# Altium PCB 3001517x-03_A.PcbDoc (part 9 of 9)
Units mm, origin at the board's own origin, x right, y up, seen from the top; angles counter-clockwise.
Board outline 100 x 72 mm, 10 copper layers (Top, GND_2, Signal_3, Signal_4, PWR_5, GND_6, Signal_7, Signal_8, GND_9, Bottom), stack 1.6 mm thick; 602 components, 497 nets, 2372 pads, 1602 vias.
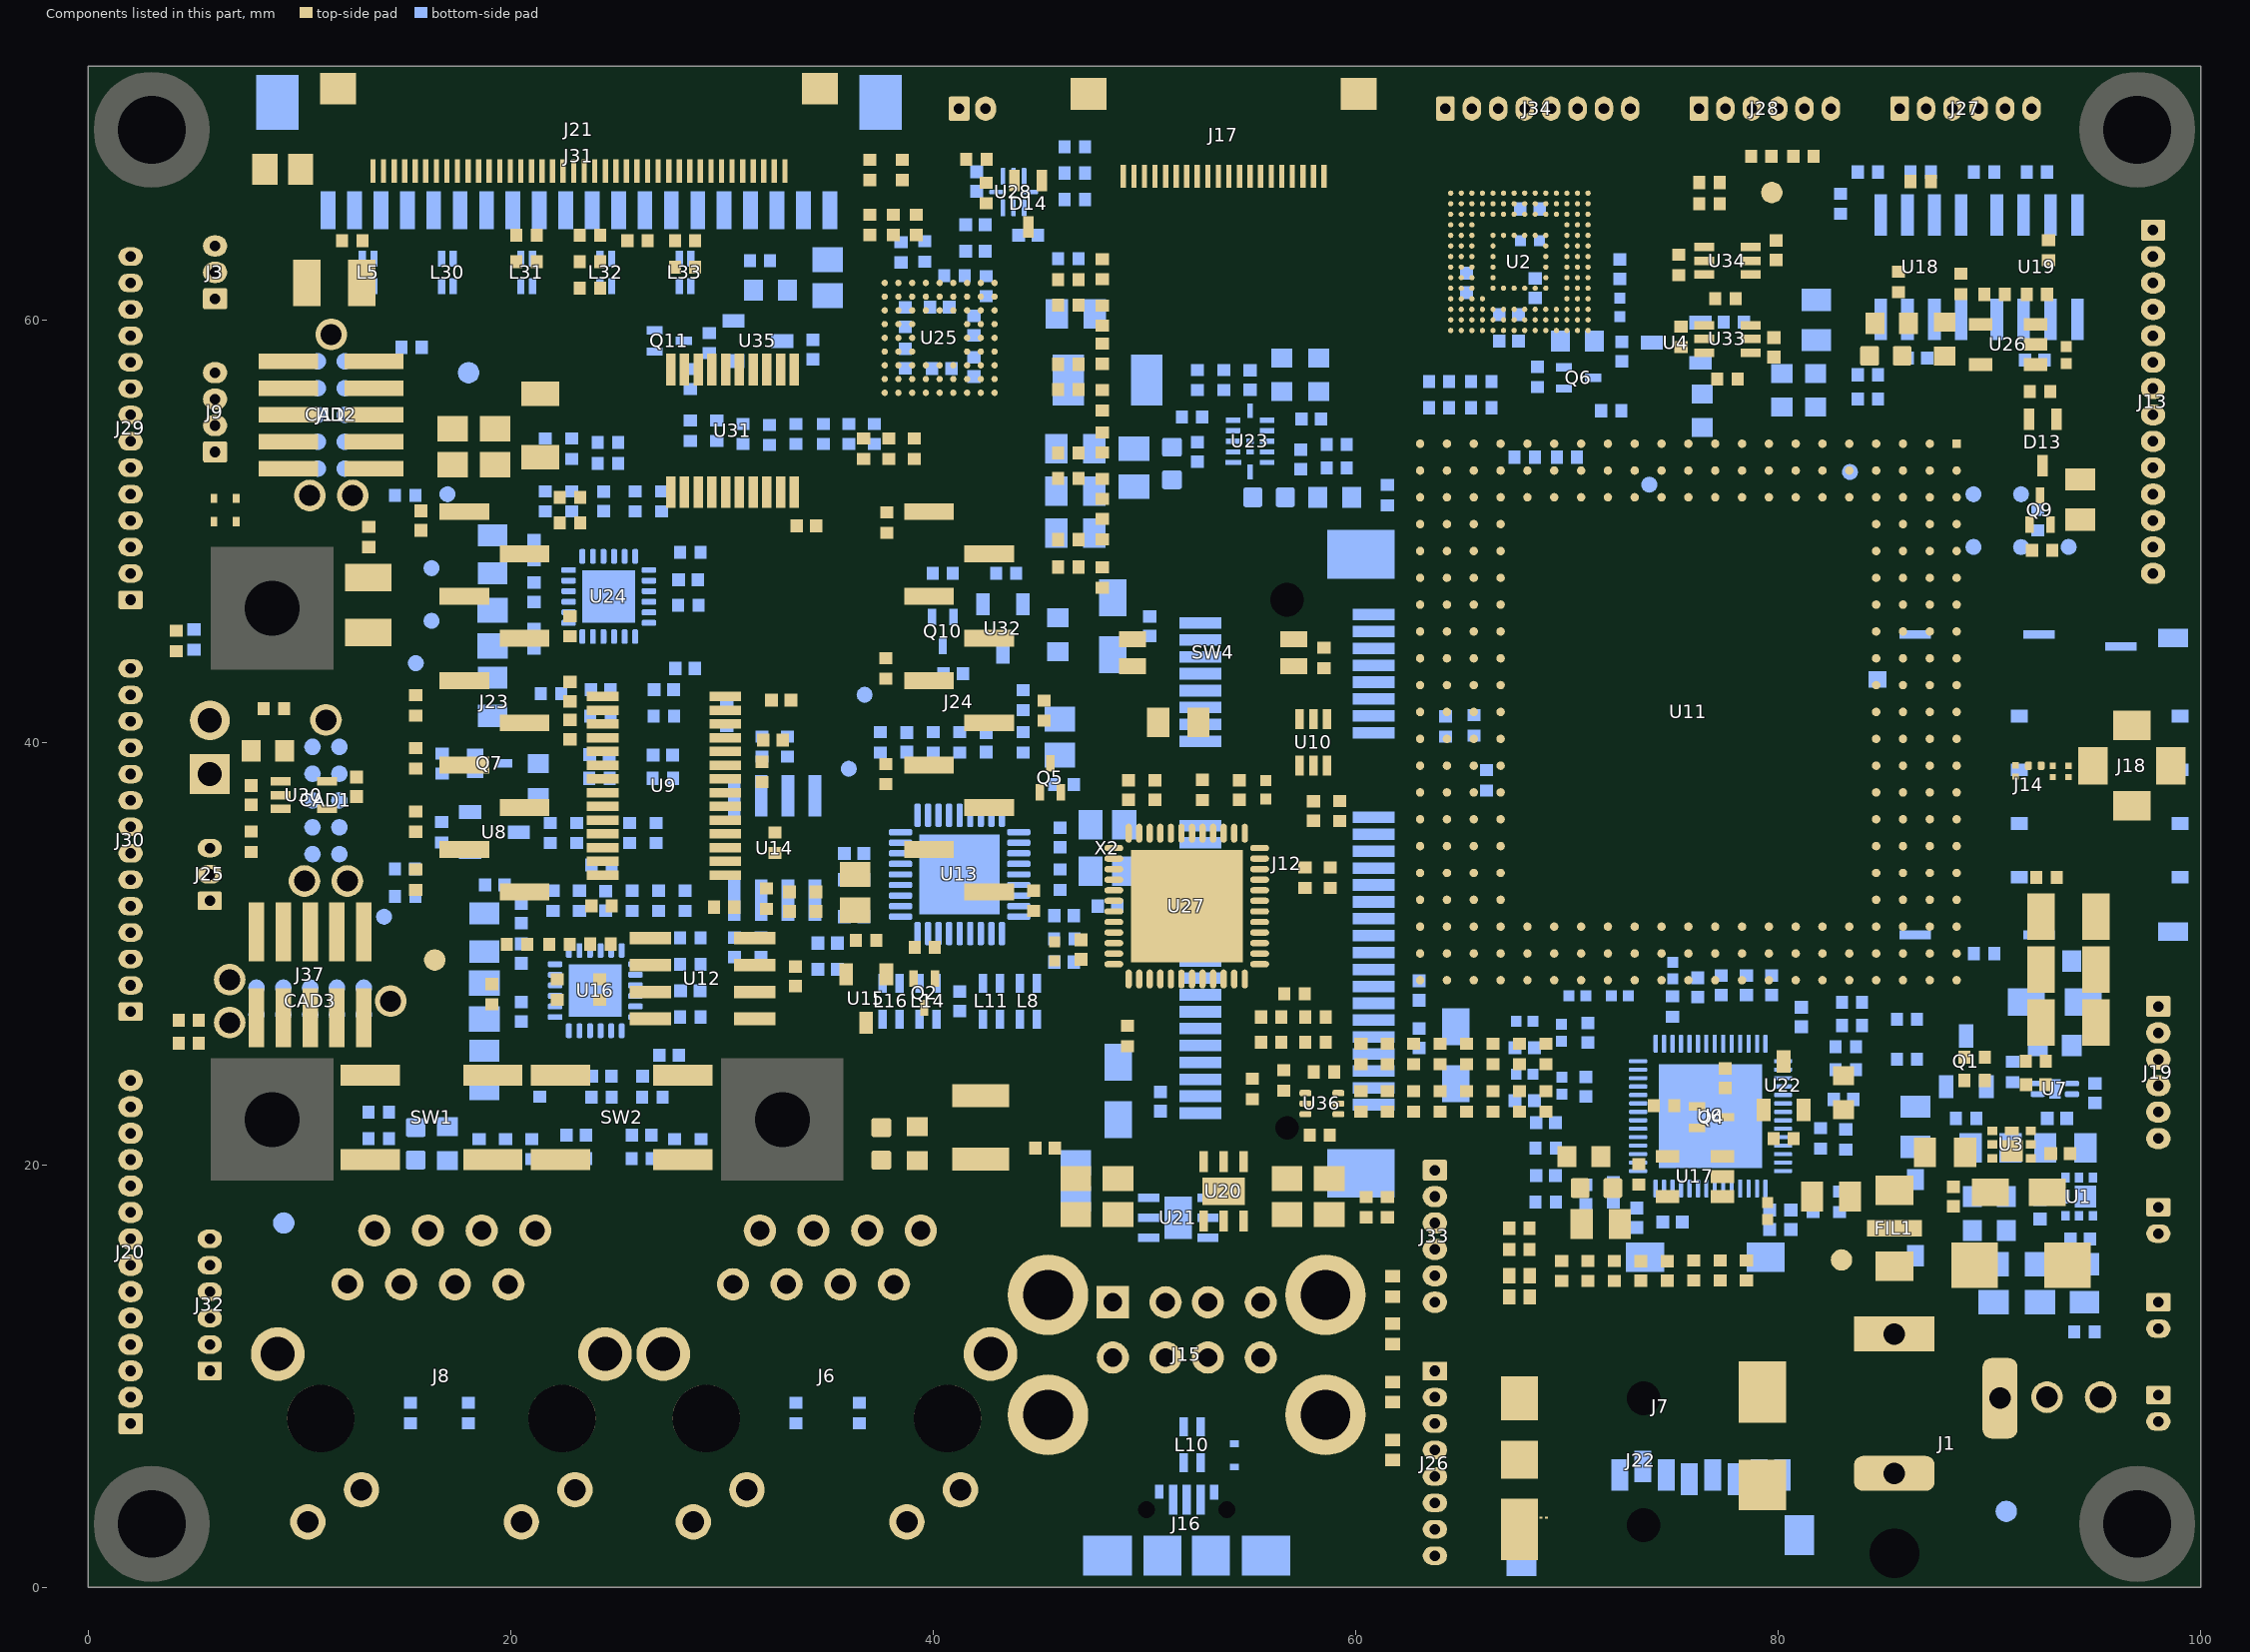
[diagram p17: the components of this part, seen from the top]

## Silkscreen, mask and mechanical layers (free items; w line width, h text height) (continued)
Sheet Graphics:
  drawing of 726 lines, arcs and shapes, not listed
  text "1" at 333.273,124.993 h4.57
  text "4" at -85.192,124.358 h4.57
  text "3" at 57.048,124.358 h4.57
  text "2" at 196.113,123.723 h4.57
  text "D" at -145.517,85.623 h7.11
  text "D" at 399.821,81.178 h7.11
  text "CUT OUT" at 45.695,72.644 h1.25
  text "CUT OUT" at 1.27,72.593 h1.25
  text "CUT OUT" at 153.492,72.593 h1.25
  text "CUT OUT" at 254.356,72.593 h1.25
  text "CUT OUT" at 101.981,63.754 h1.25 r90
  text "CUT OUT" at 204.394,63.703 h1.25 r90
  text "CUT OUT" at 306.908,63.043 h1.25 r90
  text "CUT OUT" at 71,39.5 h1.5
  text "CUT OUT" at 204.445,31.521 h1.25 r90
  text "CUT OUT" at -0.66,30.734 h1.25 r90
  text "CUT OUT" at 306.934,28.245 h1.25 r90
  text "CUT OUT" at 101.981,27.584 h1.25 r90
  text "CUT OUT" at 25.248,-2.616 h1.5
  text "CUT OUT" at 107.823,-2.718 h1.5
  text "CUT OUT" at 213.639,-2.896 h1.5
  text "CUT OUT" at 286.233,-2.896 h1.5
  text "C" at -145.517,-23.597 h7.11
  text "C" at 398.551,-23.597 h7.11
  text "1. Manufacture in accordance with IPC-6012, class 2. Inspect to IPC-A-600, class 2." at 185,-30 h6
  text "2. Manufacturing process and materials used must comply with ROHS directive / 2002/95/EC." at 185,-45 h6
  text "3. MATERIAL: ITEQ IT-180A /     Material should comply with IPC-4104/99/101/126 /     See Stack-up for details." at 185,-65 h6
  text "4. SURFACE FINISH: Apply ENIG to all exposed copper per IPC-4552." at 185,-72.5 h6
  text "5. Starting copper weight is 1/2oz. on all layers" at 185,-80 h6
  text "T" at -124.657,-87.923 h1.72
  text "a" at -123.97,-87.923 h1.72
  text "r" at -123.282,-87.923 h1.72
  text "g" at -122.791,-87.923 h1.72
  text "e" at -122.103,-87.923 h1.72
  text "t" at -121.317,-87.923 h1.72
  text "T" at -118.513,-87.923 h1.72
  text "o" at -117.825,-87.923 h1.72
  text "l" at -117.039,-87.923 h1.72
  text "+" at -116.352,-87.923 h1.72
  text "/" at -115.664,-87.923 h1.72
  text "-" at -115.074,-87.923 h1.72
  text "%" at -114.583,-87.923 h1.72
  text "L" at -112.82,-87.923 h1.72
  text "a" at -112.231,-87.923 h1.72
  text "y" at -111.543,-87.923 h1.72
  text "e" at -110.855,-87.923 h1.72
  text "r" at -110.069,-87.923 h1.72
  text "N" at -109.283,-87.923 h1.72
  text "o" at -108.301,-87.923 h1.72
  text "." at -107.515,-87.923 h1.72
  text "T" at -106.405,-87.923 h1.72
  text "r" at -105.717,-87.923 h1.72
  text "a" at -105.226,-87.923 h1.72
  text "c" at -104.538,-87.923 h1.72
  text "e" at -103.949,-87.923 h1.72
  text "C" at -102.868,-87.923 h1.72
  text "l" at -102.082,-87.923 h1.72
  text "e" at -101.689,-87.923 h1.72
  text "a" at -100.903,-87.923 h1.72
  text "r" at -100.215,-87.923 h1.72
  text "a" at -99.724,-87.923 h1.72
  text "n" at -99.036,-87.923 h1.72
  text "c" at -98.25,-87.923 h1.72
  text "e" at -97.661,-87.923 h1.72
  text "T" at -95.652,-87.923 h1.72
  text "r" at -94.964,-87.923 h1.72
  text "a" at -94.473,-87.923 h1.72
  text "c" at -93.785,-87.923 h1.72
  text "e" at -93.196,-87.923 h1.72
  text "W" at -92.115,-87.923 h1.72
  text "i" at -90.74,-87.923 h1.72
  text "d" at -90.347,-87.923 h1.72
  text "t" at -89.561,-87.923 h1.72
  text "h" at -89.069,-87.923 h1.72
  text "C" at -85.08,-87.923 h1.72
  text "h" at -84.294,-87.923 h1.72
  text "a" at -83.508,-87.923 h1.72
  text "r" at -82.82,-87.923 h1.72
  text "a" at -82.329,-87.923 h1.72
  text "c" at -81.641,-87.923 h1.72
  text "t" at -81.052,-87.923 h1.72
  text "e" at -80.561,-87.923 h1.72
  text "r" at -79.775,-87.923 h1.72
  text "i" at -79.283,-87.923 h1.72
  text "s" at -78.89,-87.923 h1.72
  text "t" at -78.301,-87.923 h1.72
  text "i" at -77.81,-87.923 h1.72
  text "c" at -77.417,-87.923 h1.72
  text "E" at -74.327,-87.923 h1.72
  text "d" at -73.639,-87.923 h1.72
  text "g" at -72.853,-87.923 h1.72
  text "e" at -72.166,-87.923 h1.72
  text "C" at -71.085,-87.923 h1.72
  text "o" at -70.299,-87.923 h1.72
  text "u" at -69.513,-87.923 h1.72
  text "p" at -68.727,-87.923 h1.72
  text "l" at -67.941,-87.923 h1.72
  text "e" at -67.548,-87.923 h1.72
  text "d" at -66.762,-87.923 h1.72
  text "I" at -126.013,-89.888 h1.72
  text "m" at -125.62,-89.888 h1.72
  text "p" at -124.441,-89.888 h1.72
  text "e" at -123.655,-89.888 h1.72
  text "d" at -122.869,-89.888 h1.72
  text "a" at -122.083,-89.888 h1.72
  text "n" at -121.395,-89.888 h1.72
  text "c" at -120.609,-89.888 h1.72
  text "e" at -120.02,-89.888 h1.72
  text "(" at -103.513,-89.888 h1.72
  text "M" at -103.022,-89.888 h1.72
  text "I" at -101.745,-89.888 h1.72
  text "L" at -101.352,-89.888 h1.72
  text ")" at -100.762,-89.888 h1.72
  text "(" at -93.754,-89.888 h1.72
  text "M" at -93.263,-89.888 h1.72
  text "I" at -91.986,-89.888 h1.72
  text "L" at -91.593,-89.888 h1.72
  text ")" at -91.004,-89.888 h1.72
  text "I" at -85.712,-89.888 h1.72
  text "m" at -85.319,-89.888 h1.72
  text "p" at -84.141,-89.888 h1.72
  text "e" at -83.355,-89.888 h1.72
  text "d" at -82.569,-89.888 h1.72
  text "a" at -81.783,-89.888 h1.72
  text "n" at -81.095,-89.888 h1.72
  text "c" at -80.309,-89.888 h1.72
  text "e" at -79.719,-89.888 h1.72
  text "(" at -78.639,-89.888 h1.72
  text "Z" at -78.147,-89.888 h1.72
  text "o" at -77.46,-89.888 h1.72
  text ")" at -76.674,-89.888 h1.72
  text "D" at -73.695,-89.888 h1.72
  text "i" at -72.81,-89.888 h1.72
  text "f" at -72.417,-89.888 h1.72
  text "f" at -71.926,-89.888 h1.72
  text "e" at -71.435,-89.888 h1.72
  text "r" at -70.649,-89.888 h1.72
  text "e" at -70.158,-89.888 h1.72
  text "n" at -69.372,-89.888 h1.72
  text "t" at -68.586,-89.888 h1.72
  text "i" at -68.095,-89.888 h1.72
  text "a" at -67.702,-89.888 h1.72
  text "l" at -67.014,-89.888 h1.72
  text "(" at -72.249,-91.853 h1.72
  text "Z" at -71.758,-91.853 h1.72
  text "d" at -71.07,-91.853 h1.72
  text "i" at -70.284,-91.853 h1.72
  text "f" at -69.891,-91.853 h1.72
  text "f" at -69.4,-91.853 h1.72
  text ")" at -68.909,-91.853 h1.72
  text "D" at -126.645,-93.916 h1.72
  text "I" at -125.761,-93.916 h1.72
  text "F" at -125.368,-93.916 h1.72
  text "F" at -124.68,-93.916 h1.72
  text "_" at -123.993,-93.916 h1.72
  text "1" at -123.305,-93.916 h1.72
  text "0" at -122.617,-93.916 h1.72
  text "0" at -121.929,-93.916 h1.72
  text "o" at -121.242,-93.916 h1.72
  text "h" at -120.456,-93.916 h1.72
  text "m" at -119.67,-93.916 h1.72
  text "1" at -116.796,-93.916 h1.72
  text "0" at -116.108,-93.916 h1.72
  text "3" at -110.471,-93.916 h1.72
  text "8" at -102.248,-93.916 h1.72
  text "5" at -92.58,-93.916 h1.72
  text "5" at -82.731,-93.916 h1.72
  text "5" at -82.043,-93.916 h1.72
  text "." at -81.355,-93.916 h1.72
  text "3" at -80.962,-93.916 h1.72
  text "6" at -80.274,-93.916 h1.72
  text "1" at -72.159,-93.916 h1.72
  text "0" at -71.471,-93.916 h1.72
  text "0" at -70.783,-93.916 h1.72
  text "." at -70.095,-93.916 h1.72
  text "3" at -69.702,-93.916 h1.72
  text "8" at -69.015,-93.916 h1.72
  text "6. SOLDER MASK: LPI over bare copper. / SOLDER MASK COLOR: BLUE" at 185,-95 h6
  text "D" at -126.645,-95.881 h1.72
  text "I" at -125.761,-95.881 h1.72
  text "F" at -125.368,-95.881 h1.72
  text "F" at -124.68,-95.881 h1.72
  text "_" at -123.993,-95.881 h1.72
  text "1" at -123.305,-95.881 h1.72
  text "0" at -122.617,-95.881 h1.72
  text "0" at -121.929,-95.881 h1.72
  text "o" at -121.242,-95.881 h1.72
  text "h" at -120.456,-95.881 h1.72
  text "m" at -119.67,-95.881 h1.72
  text "1" at -116.796,-95.881 h1.72
  text "0" at -116.108,-95.881 h1.72
  text "8" at -110.471,-95.881 h1.72
  text "8" at -102.248,-95.881 h1.72
  text "5" at -92.58,-95.881 h1.72
  text "5" at -82.731,-95.881 h1.72
  text "5" at -82.043,-95.881 h1.72
  text "." at -81.355,-95.881 h1.72
  text "3" at -80.962,-95.881 h1.72
  text "6" at -80.274,-95.881 h1.72
  text "1" at -72.159,-95.881 h1.72
  text "0" at -71.471,-95.881 h1.72
  text "0" at -70.783,-95.881 h1.72
  text "." at -70.095,-95.881 h1.72
  text "3" at -69.702,-95.881 h1.72
  text "8" at -69.015,-95.881 h1.72
  text "D" at -126.284,-97.846 h1.72
  text "I" at -125.4,-97.846 h1.72
  text "F" at -125.007,-97.846 h1.72
  text "F" at -124.319,-97.846 h1.72
  text "_" at -123.631,-97.846 h1.72
  text "9" at -122.943,-97.846 h1.72
  text "0" at -122.256,-97.846 h1.72
  text "o" at -121.568,-97.846 h1.72
  text "h" at -120.782,-97.846 h1.72
  text "m" at -119.996,-97.846 h1.72
  text "1" at -116.796,-97.846 h1.72
  text "0" at -116.108,-97.846 h1.72
  text "3" at -110.471,-97.846 h1.72
  text "8" at -102.248,-97.846 h1.72
  text "6" at -93.032,-97.846 h1.72
  text "." at -92.344,-97.846 h1.72
  text "5" at -91.951,-97.846 h1.72
  text "4" at -82.731,-97.846 h1.72
  text "8" at -82.043,-97.846 h1.72
  text "." at -81.355,-97.846 h1.72
  text "8" at -80.962,-97.846 h1.72
  text "8" at -80.274,-97.846 h1.72
  text "8" at -71.887,-97.846 h1.72
  text "9" at -71.2,-97.846 h1.72
  text "." at -70.512,-97.846 h1.72
  text "7" at -70.119,-97.846 h1.72
  text "6" at -69.431,-97.846 h1.72
  text "D" at -126.284,-99.811 h1.72
  text "I" at -125.4,-99.811 h1.72
  text "F" at -125.007,-99.811 h1.72
  text "F" at -124.319,-99.811 h1.72
  text "_" at -123.631,-99.811 h1.72
  text "9" at -122.943,-99.811 h1.72
  text "0" at -122.256,-99.811 h1.72
  text "o" at -121.568,-99.811 h1.72
  text "h" at -120.782,-99.811 h1.72
  text "m" at -119.996,-99.811 h1.72
  text "1" at -116.796,-99.811 h1.72
  text "0" at -116.108,-99.811 h1.72
  text "7" at -110.471,-99.811 h1.72
  text "8" at -102.248,-99.811 h1.72
  text "6" at -93.032,-99.811 h1.72
  text "." at -92.344,-99.811 h1.72
  text "5" at -91.951,-99.811 h1.72
  text "4" at -82.731,-99.811 h1.72
  text "8" at -82.043,-99.811 h1.72
  text "." at -81.355,-99.811 h1.72
  text "8" at -80.962,-99.811 h1.72
  text "8" at -80.274,-99.811 h1.72
  text "8" at -71.887,-99.811 h1.72
  text "9" at -71.2,-99.811 h1.72
  text "." at -70.512,-99.811 h1.72
  text "7" at -70.119,-99.811 h1.72
  text "6" at -69.431,-99.811 h1.72
  text "D" at -126.284,-101.776 h1.72
  text "I" at -125.4,-101.776 h1.72
  text "F" at -125.007,-101.776 h1.72
  text "F" at -124.319,-101.776 h1.72
  text "_" at -123.631,-101.776 h1.72
  text "9" at -122.943,-101.776 h1.72
  text "0" at -122.256,-101.776 h1.72
  text "o" at -121.568,-101.776 h1.72
  text "h" at -120.782,-101.776 h1.72
  text "m" at -119.996,-101.776 h1.72
  text "1" at -116.796,-101.776 h1.72
  text "0" at -116.108,-101.776 h1.72
  text "8" at -110.471,-101.776 h1.72
  text "8" at -102.248,-101.776 h1.72
  text "6" at -93.032,-101.776 h1.72
  text "." at -92.344,-101.776 h1.72
  text "5" at -91.951,-101.776 h1.72
  text "4" at -82.731,-101.776 h1.72
  text "8" at -82.043,-101.776 h1.72
  text "." at -81.355,-101.776 h1.72
  text "8" at -80.962,-101.776 h1.72
  text "8" at -80.274,-101.776 h1.72
  text "8" at -71.887,-101.776 h1.72
  text "9" at -71.2,-101.776 h1.72
  text "." at -70.512,-101.776 h1.72
  text "7" at -70.119,-101.776 h1.72
  text "6" at -69.431,-101.776 h1.72
  text "D" at -126.284,-103.741 h1.72
  text "I" at -125.4,-103.741 h1.72
  text "F" at -125.007,-103.741 h1.72
  text "F" at -124.319,-103.741 h1.72
  text "_" at -123.631,-103.741 h1.72
  text "9" at -122.943,-103.741 h1.72
  text "0" at -122.256,-103.741 h1.72
  text "o" at -121.568,-103.741 h1.72
  text "h" at -120.782,-103.741 h1.72
  text "m" at -119.996,-103.741 h1.72
  text "1" at -116.796,-103.741 h1.72
  text "0" at -116.108,-103.741 h1.72
  text "1" at -110.742,-103.741 h1.72
  text "0" at -110.054,-103.741 h1.72
  text "8" at -102.248,-103.741 h1.72
  text "5" at -92.58,-103.741 h1.72
  text "4" at -82.731,-103.741 h1.72
  text "8" at -82.043,-103.741 h1.72
  text "." at -81.355,-103.741 h1.72
  text "9" at -80.962,-103.741 h1.72
  text "5" at -80.274,-103.741 h1.72
  text "9" at -71.887,-103.741 h1.72
  text "0" at -71.2,-103.741 h1.72
  text "." at -70.512,-103.741 h1.72
  text "5" at -70.119,-103.741 h1.72
  text "2" at -69.431,-103.741 h1.72
  text "5" at -126.645,-105.706 h1.72
  text "0" at -125.958,-105.706 h1.72
  text "o" at -125.27,-105.706 h1.72
  text "h" at -124.484,-105.706 h1.72
  text "m" at -123.698,-105.706 h1.72
  text "_" at -122.519,-105.706 h1.72
  text "C" at -121.831,-105.706 h1.72
  text "H" at -121.045,-105.706 h1.72
  text "A" at -120.161,-105.706 h1.72
  text "R" at -119.277,-105.706 h1.72
  text "1" at -116.796,-105.706 h1.72
  text "0" at -116.108,-105.706 h1.72
  text "1" at -110.471,-105.706 h1.72
  text "N" at -103.061,-105.706 h1.72
  text "/" at -102.079,-105.706 h1.72
  text "A" at -101.49,-105.706 h1.72
  text "4" at -93.032,-105.706 h1.72
  text "." at -92.344,-105.706 h1.72
  text "7" at -91.951,-105.706 h1.72
  text "5" at -82.731,-105.706 h1.72
  text "0" at -82.043,-105.706 h1.72
  text "." at -81.355,-105.706 h1.72
  text "4" at -80.962,-105.706 h1.72
  text "3" at -80.274,-105.706 h1.72
  text "N" at -71.526,-105.706 h1.72
  text "/" at -70.544,-105.706 h1.72
  text "A" at -69.954,-105.706 h1.72
  text "5" at -126.645,-107.671 h1.72
  text "0" at -125.958,-107.671 h1.72
  text "o" at -125.27,-107.671 h1.72
  text "h" at -124.484,-107.671 h1.72
  text "m" at -123.698,-107.671 h1.72
  text "_" at -122.519,-107.671 h1.72
  text "C" at -121.831,-107.671 h1.72
  text "H" at -121.045,-107.671 h1.72
  text "A" at -120.161,-107.671 h1.72
  text "R" at -119.277,-107.671 h1.72
  text "1" at -116.796,-107.671 h1.72
  text "0" at -116.108,-107.671 h1.72
  text "3" at -110.471,-107.671 h1.72
  text "N" at -103.061,-107.671 h1.72
  text "/" at -102.079,-107.671 h1.72
  text "A" at -101.49,-107.671 h1.72
  text "5" at -92.58,-107.671 h1.72
  text "4" at -82.731,-107.671 h1.72
  text "8" at -82.043,-107.671 h1.72
  text "." at -81.355,-107.671 h1.72
  text "3" at -80.962,-107.671 h1.72
  text "8" at -80.274,-107.671 h1.72
  text "N" at -71.526,-107.671 h1.72
  text "/" at -70.544,-107.671 h1.72
  text "A" at -69.954,-107.671 h1.72
  text "5" at -126.645,-109.636 h1.72
  text "0" at -125.958,-109.636 h1.72
  text "o" at -125.27,-109.636 h1.72
  text "h" at -124.484,-109.636 h1.72
  text "m" at -123.698,-109.636 h1.72
  text "_" at -122.519,-109.636 h1.72
  text "C" at -121.831,-109.636 h1.72
  text "H" at -121.045,-109.636 h1.72
  text "A" at -120.161,-109.636 h1.72
  text "R" at -119.277,-109.636 h1.72
  text "1" at -116.796,-109.636 h1.72
  text "0" at -116.108,-109.636 h1.72
  text "7" at -110.471,-109.636 h1.72
  text "N" at -103.061,-109.636 h1.72
  text "/" at -102.079,-109.636 h1.72
  text "A" at -101.49,-109.636 h1.72
  text "5" at -92.58,-109.636 h1.72
  text "5" at -82.731,-109.636 h1.72
  text "0" at -82.043,-109.636 h1.72
  text "." at -81.355,-109.636 h1.72
  text "3" at -80.962,-109.636 h1.72
  text "5" at -80.274,-109.636 h1.72
  text "N" at -71.526,-109.636 h1.72
  text "/" at -70.544,-109.636 h1.72
  text "A" at -69.954,-109.636 h1.72
  text "5" at -126.645,-111.601 h1.72
  text "0" at -125.958,-111.601 h1.72
  text "o" at -125.27,-111.601 h1.72
  text "h" at -124.484,-111.601 h1.72
  text "m" at -123.698,-111.601 h1.72
  text "_" at -122.519,-111.601 h1.72
  text "C" at -121.831,-111.601 h1.72
  text "H" at -121.045,-111.601 h1.72
  text "A" at -120.161,-111.601 h1.72
  text "R" at -119.277,-111.601 h1.72
  text "1" at -116.796,-111.601 h1.72
  text "0" at -116.108,-111.601 h1.72
  text "8" at -110.471,-111.601 h1.72
  text "N" at -103.061,-111.601 h1.72
  text "/" at -102.079,-111.601 h1.72
  text "A" at -101.49,-111.601 h1.72
  text "5" at -92.58,-111.601 h1.72
  text "5" at -82.731,-111.601 h1.72
  text "0" at -82.043,-111.601 h1.72
  text "." at -81.355,-111.601 h1.72
  text "3" at -80.962,-111.601 h1.72
  text "5" at -80.274,-111.601 h1.72
  text "N" at -71.526,-111.601 h1.72
  text "/" at -70.544,-111.601 h1.72
  text "A" at -69.954,-111.601 h1.72
  text "5" at -126.645,-113.565 h1.72
  text "0" at -125.958,-113.565 h1.72
  text "o" at -125.27,-113.565 h1.72
  text "h" at -124.484,-113.565 h1.72
  text "m" at -123.698,-113.565 h1.72
  text "_" at -122.519,-113.565 h1.72
  text "C" at -121.831,-113.565 h1.72
  text "H" at -121.045,-113.565 h1.72
  text "A" at -120.161,-113.565 h1.72
  text "R" at -119.277,-113.565 h1.72
  text "1" at -116.796,-113.565 h1.72
  text "0" at -116.108,-113.565 h1.72
  text "1" at -110.742,-113.565 h1.72
  text "0" at -110.054,-113.565 h1.72
  text "N" at -103.061,-113.565 h1.72
  text "/" at -102.079,-113.565 h1.72
  text "A" at -101.49,-113.565 h1.72
  text "4" at -93.032,-113.565 h1.72
  text "." at -92.344,-113.565 h1.72
  text "7" at -91.951,-113.565 h1.72
  text "5" at -82.731,-113.565 h1.72
  text "0" at -82.043,-113.565 h1.72
  text "." at -81.355,-113.565 h1.72
  text "4" at -80.962,-113.565 h1.72
  text "3" at -80.274,-113.565 h1.72
  text "N" at -71.526,-113.565 h1.72
  text "/" at -70.544,-113.565 h1.72
  text "A" at -69.954,-113.565 h1.72
  text "7. SILKSCREEN: Apply on top and bottom sides of PCB. / High accuracy required for QR code on Bottom Overlay. / SILKSCREEN COLOR: WHITE" at 185,-117.5 h6
  text "Layer" at -125.494,-122 h2
  text "Name" at -111.989,-122 h2
  text "Material" at -81.156,-122 h2
  text "Thickness" at -18,-122 h2
  text "Constant" at 3.503,-122 h2
  text "Board Layer Stack" at 22.339,-122 h2
  text "1" at -125.494,-126 h2
  text "Top Overlay" at -111.989,-126 h2
  text "B" at -145.517,-129.642 h7.11
  text "B" at 398.551,-129.642 h7.11
  text "2" at -125.494,-130 h2
  text "Top Solder" at -111.989,-130 h2
  text "Dielectric" at -81.156,-130 h2
  text "0.50mil" at -18,-130 h2
  text "3.3" at 3.503,-130 h2
  text "8. GERBER FILE FORMAT: 274-X WITH 4/3 accuracy (XXXX.XXX). / Gerber and drill in mm." at 185,-132.5 h6
  text "3" at -125.494,-134 h2
  text "Top" at -111.989,-134 h2
  text "Copper" at -81.156,-134 h2
  text "1.70mil" at -18,-134 h2
  text "4" at -125.494,-138 h2
  text "Dielectric1" at -111.989,-138 h2
  text "IT-180A; 1086; Rc62%; (2GHz)" at -81.156,-138 h2
  text "2.99mil" at -18,-138 h2
  text "3.9" at 3.503,-138 h2
  text "5" at -125.494,-142 h2
  text "GND_2" at -111.989,-142 h2
  text "Copper" at -81.156,-142 h2
  text "0.70mil" at -18,-142 h2
  text "9. Maximum warp and twist per IPC-6012 of 0.75% inch/inch." at 185,-142.5 h6
  text "6" at -125.494,-146 h2
  text "Dielectric2" at -111.989,-146 h2
  text "IT-180A; 2-1080; (2GHz)" at -81.156,-146 h2
  text "5.00mil" at -18,-146 h2
  text "3.7" at 3.503,-146 h2
  text "7" at -125.494,-150 h2
  text "Signal_3" at -111.989,-150 h2
  text "Copper" at -81.156,-150 h2
  text "0.70mil" at -18,-150 h2
  text "8" at -125.494,-154 h2
  text "Dielectric3" at -111.989,-154 h2
  text "IT-180A; 1067; Rc71%; (2GHz) x2" at -81.156,-154 h2
  text "5.00mil" at -18,-154 h2
  text "3.9" at 3.503,-154 h2
  text "9" at -125.494,-158 h2
  text "Signal_4" at -111.989,-158 h2
  text "Copper" at -81.156,-158 h2
  text "0.70mil" at -18,-158 h2
  text "10. Copper thieving is NOT allowed within board outline. / Thieving may be placed in array rails." at 185,-160 h6
  text "10" at -125.494,-162 h2
  text "Dielectric 13" at -111.989,-162 h2
  text "IT-180A; 2-1080; (2GHz)" at -81.156,-162 h2
  text "5.00mil" at -18,-162 h2
  text "3.7" at 3.503,-162 h2
  text "11" at -125.494,-166 h2
  text "PWR_5" at -111.989,-166 h2
  text "Copper" at -81.156,-166 h2
  text "0.70mil" at -18,-166 h2
  text "12" at -125.494,-170 h2
  text "Dielectric6" at -111.989,-170 h2
  text "IT-180A" at -81.156,-170 h2
  text "17.99mil" at -18,-170 h2
  text "3.9" at 3.503,-170 h2
  text "13" at -125.494,-174 h2
  text "GND_6" at -111.989,-174 h2
  text "Copper" at -81.156,-174 h2
  text "0.70mil" at -18,-174 h2
  text "14" at -125.494,-178 h2
  text "Dielectric9" at -111.989,-178 h2
  text "IT-180A; 2-1080; (2GHz)" at -81.156,-178 h2
  text "5.00mil" at -18,-178 h2
  text "3.7" at 3.503,-178 h2
  text "15" at -125.494,-182 h2
  text "Signal_7" at -111.989,-182 h2
  text "Copper" at -81.156,-182 h2
  text "0.70mil" at -18,-182 h2
  text "11. Plated holes are specified as finished hole sizes (see table). / Plated hole tolerance ±0.003\" (±76µm) / NPTH tolerance ±0.0015\" (±38.1µm)" at 185,-182.5 h6
  text "16" at -125.494,-186 h2
  text "Dielectric10" at -111.989,-186 h2
  text "IT-180A; 1067; Rc71%; (2GHz) x2" at -81.156,-186 h2
  text "5.00mil" at -18,-186 h2
  text "3.9" at 3.503,-186 h2
  text "17" at -125.494,-190 h2
  text "Signal_8" at -111.989,-190 h2
  text "Copper" at -81.156,-190 h2
  text "0.70mil" at -18,-190 h2
  text "12. Slot/Cut-Out tolerance ±0.005\" (±127µm)" at 185,-190 h6
  text "18" at -125.494,-194 h2
  text "Dielectric 12" at -111.989,-194 h2
  text "IT-180A; 2-1080; (2GHz)" at -81.156,-194 h2
  text "5.00mil" at -18,-194 h2
  text "3.7" at 3.503,-194 h2
  text "19" at -125.494,-198 h2
  text "GND_9" at -111.989,-198 h2
  text "Copper" at -81.156,-198 h2
  text "0.70mil" at -18,-198 h2
  text "13. See table for controlled impedance trace widths." at 185,-200 h6
  text "20" at -125.494,-202 h2
  text "Dielectric11" at -111.989,-202 h2
  text "IT-180A; 1086; Rc62%; (2GHz)" at -81.156,-202 h2
  text "2.99mil" at -18,-202 h2
  text "3.9" at 3.503,-202 h2
  text "21" at -125.494,-206 h2
  text "Bottom" at -111.989,-206 h2
  text "Copper" at -81.156,-206 h2
  text "1.70mil" at -18,-206 h2
  text "14. Finished thickness is 0.062\" ±0.006\" (1.57 ± 157µm)" at 185,-207.5 h6
  text "22" at -125.494,-210 h2
  text "Bottom Solder" at -111.989,-210 h2
  text "Dielectric" at -81.156,-210 h2
  text "0.50mil" at -18,-210 h2
  text "3.3" at 3.503,-210 h2
  text "23" at -125.494,-214 h2
  text "Bottom Overlay" at -111.989,-214 h2
  text "15. Intentional short: NetNT1-1 to GND" at 185,-215 h6
  text "A" at -145.085,-222.352 h7.11
  text "A" at 398.983,-222.352 h7.11
  text "CAD GENERATED:" at 337.718,-227.432 h1.27
  text "CAD GENERATED:" at 337.718,-227.432 h1.27
  text ".pcb_File_Name_No_Path" at 353.212,-227.432 h2.17
  text "EXCEPT AS MAY BE OTHERWISE PROVIDED BY" at 238.658,-231.496 h2.17
  text "WIRELESS DESIGN SERVICES" at 332.638,-233.02 h2.54
  text "CONTRACT, THIS DOCUMENT IS THE PROPERTY" at 238.658,-233.528 h2.17
  text "OF DIGI INTERNATIONAL.  IF RELEASED TO OTHER" at 238.658,-235.56 h2.17
  text "11001 Bren Road East" at 332.638,-236.576 h2.54
  text "SOURCES, IT SHALL BE RECEIVED BY SUCH" at 238.658,-237.592 h2.17
  text "SOURCES IN TOTAL CONFIDENCE AND SHALL NOT" at 238.658,-239.624 h2.17
  text "Minnetonka, MN 55343" at 333.146,-240.132 h2.54
  text "BE RELEASED TO ANY THIRD PARTY OR PARTIES," at 238.658,-241.656 h2.17
  text "NOR USED FOR MANUFACTURE OR SALE OF THE" at 238.658,-243.688 h2.17
  text "ARTICLES WITHOUT PRIOR WRITTEN" at 238.658,-245.72 h2.17
  text "DIGI INTERNATIONAL" at 328.574,-246.228 h2.54
  text "AUTHORIZATION." at 238.658,-247.752 h2.17
  text "ConnectCore for i.MX6UL" at 323.596,-250.444 h2.54
  text "ENGINEER" at 238.15,-254.356 h1.27
  text "SINGLE BOARD COMPUTER (SBC)" at 315.976,-254.508 h2.54
  text "SEBASTIEN MEYER" at 255.524,-255.016 h1.27
  text "PCB DESIGNER" at 238.15,-259.436 h1.27
  text "SIZE" at 291.49,-259.436 h1.27
  text "CAGE NO." at 299.618,-259.436 h1.27
  text "PCB NO." at 327.558,-259.436 h1.27
  text "REV." at 389.534,-259.436 h1.27
  text "JOSH FLAGSTAD" at 255.524,-260.096 h1.27
  text "30015172-03" at 343.5,-263.5 h2.54
  text "DATE" at 238.15,-264.008 h1.27
  text "C" at 291.998,-264.008 h2.54
  text "A" at 389.534,-264.008 h2.54
  text ".Print_Date" at 254.914,-265.024 h1.27
  text "JIRA EPIC:" at 238.15,-269.088 h1.27
  text "CC6UL-244" at 254.914,-270.612 h1.27
  text ".Print_Scale" at 289.458,-270.612 h1.27
  text "SVN HEAD REV:" at 314.858,-270.612 h1.27
  text ".VersionControl_RevNumber" at 330.606,-270.612 h1.27
  text "SHEET:" at 352.958,-270.612 h1.27
  text "1 OF 1" at 371.5,-270.612 h1.27
  text "1" at 333.273,-280.137 h4.57
  text "4" at -85.192,-280.772 h4.57
  text "3" at 57.048,-280.772 h4.57
  text "2" at 196.113,-281.407 h4.57
Drill Drawing:
  circle w0.1: c21.781,-72.167 r0.5
  circle w0.1: c21.781,-72.167 r0.833
  lines w0.1: 19.5,-104.125 166.639,-104.125 ; 19.5,-29.125 166.639,-29.125 ; 32.792,-107.875 32.792,-25.375 ; 48.738,-107.875 48.738,-25.375 ; 77.179,-107.875 77.179,-25.375 ; 105.621,-107.875 105.621,-25.375 ; 135.482,-107.875 135.482,-25.375 ; 147.649,-107.875 147.649,-25.375 ; 19.5,-107.875 166.639,-107.875 166.639,-25.375 19.5,-25.375 19.5,-107.875 ; 20.948,-95.083 21.365,-95.083 21.365,-95.5 22.198,-95.5 22.198,-95.083 22.615,-95.083 22.615,-94.25 22.198,-94.25 22.198,-93.833 21.365,-93.833 21.365,-94.25 20.948,-94.25 20.948,-95.083 ; 20.948,-87.583 21.365,-87.583 21.781,-88 22.198,-87.583 22.615,-87.583 22.198,-87.167 22.615,-86.75 22.198,-86.75 21.781,-86.333 21.365,-86.75 20.948,-86.75 21.365,-87.167 20.948,-87.583 ; 20.948,-61.333 21.365,-61.333 21.781,-61.75 22.198,-61.333 22.615,-61.333 22.198,-60.917 22.615,-60.5 22.198,-60.5 21.781,-60.083 21.365,-60.5 20.948,-60.5 21.365,-60.917 20.948,-61.333 ; 20.948,-54.25 22.615,-54.25 22.615,-52.583 20.948,-52.583 20.948,-54.25 ; 20.948,-35.5 21.781,-35.083 22.615,-35.5 22.198,-34.667 22.615,-33.833 21.781,-34.25 20.948,-33.833 21.365,-34.667 20.948,-35.5 ; 21.281,-61.167 21.531,-61.167 21.781,-61.417 22.031,-61.167 22.281,-61.167 22.031,-60.917 22.281,-60.667 22.031,-60.667 21.781,-60.417 21.531,-60.667 21.281,-60.667 21.531,-60.917 21.281,-61.167 ; 21.281,-35.167 21.781,-34.917 22.281,-35.167 22.031,-34.667 22.281,-34.167 21.781,-34.417 21.281,-34.167 21.531,-34.667 21.281,-35.167
  text ".Layer_Name" at 35.736,-19.262 h2.54
  text "Symbol" at 21.75,-28 h1.8
  text "Count" at 33.917,-28 h1.8
  text "Hole Size" at 49.863,-28 h1.8
  text "Hole Length" at 78.304,-28 h1.8
  text "Rout Path Length" at 106.746,-28 h1.8
  text "Plated" at 136.607,-28 h1.8
  text "Hole Type" at 148.774,-28 h1.8
  text "600" at 33.917,-31.75 h1.5
  text "0.200mm (7.87mil)" at 49.863,-31.75 h1.5
  text "-" at 78.304,-31.75 h1.5
  text "-" at 106.746,-31.75 h1.5
  text "PTH" at 136.607,-31.75 h1.5
  text "Round" at 148.774,-31.75 h1.5
  text "W" at 21.126,-31.85 h1.67
  text "1002" at 33.917,-35.5 h1.5
  text "0.250mm (9.84mil)" at 49.863,-35.5 h1.5
  text "-" at 78.304,-35.5 h1.5
  text "-" at 106.746,-35.5 h1.5
  text "PTH" at 136.607,-35.5 h1.5
  text "Round" at 148.774,-35.5 h1.5
  text "120" at 33.917,-39.25 h1.5
  text "0.500mm (19.69mil)" at 49.863,-39.25 h1.5
  text "-" at 78.304,-39.25 h1.5
  text "-" at 106.746,-39.25 h1.5
  text "PTH" at 136.607,-39.25 h1.5
  text "Round" at 148.774,-39.25 h1.5
  text "H" at 21.126,-39.35 h1.67
  text "2" at 33.917,-43 h1.5
  text "0.813mm (32.00mil)" at 49.863,-43 h1.5
  text "-" at 78.304,-43 h1.5
  text "-" at 106.746,-43 h1.5
  text "NPTH" at 136.607,-43 h1.5
  text "Round" at 148.774,-43 h1.5
  text "S" at 21.126,-43.1 h1.67
  text "10" at 33.917,-46.75 h1.5
  text "0.889mm (35.00mil)" at 49.863,-46.75 h1.5
  text "-" at 78.304,-46.75 h1.5
  text "-" at 106.746,-46.75 h1.5
  text "PTH" at 136.607,-46.75 h1.5
  text "Round" at 148.774,-46.75 h1.5
  text "K" at 21.126,-46.85 h1.67
  text "14" at 33.917,-50.5 h1.5
  text "0.900mm (35.43mil)" at 49.863,-50.5 h1.5
  text "-" at 78.304,-50.5 h1.5
  text "-" at 106.746,-50.5 h1.5
  text "PTH" at 136.607,-50.5 h1.5
  text "Round" at 148.774,-50.5 h1.5
  text "J" at 21.126,-50.6 h1.67
  text "9" at 33.917,-54.25 h1.5
  text "0.991mm (39.00mil)" at 49.863,-54.25 h1.5
  text "-" at 78.304,-54.25 h1.5
  text "-" at 106.746,-54.25 h1.5
  text "NPTH" at 136.607,-54.25 h1.5
  text "Round" at 148.774,-54.25 h1.5
  text "8" at 33.917,-58 h1.5
  text "1.016mm (40.00mil)" at 49.863,-58 h1.5
  text "-" at 78.304,-58 h1.5
  text "-" at 106.746,-58 h1.5
  text "PTH" at 136.607,-58 h1.5
  text "Round" at 148.774,-58 h1.5
  text "I" at 21.404,-58.1 h1.67
  text "2" at 33.917,-61.75 h1.5
  text "1.020mm (40.16mil)" at 49.863,-61.75 h1.5
  text "-" at 78.304,-61.75 h1.5
  text "-" at 106.746,-61.75 h1.5
  text "PTH" at 136.607,-61.75 h1.5
  text "Round" at 148.774,-61.75 h1.5
  text "1" at 33.917,-65.5 h1.5
  text "1.100mm (43.31mil)" at 49.863,-65.5 h1.5
  text "-" at 78.304,-65.5 h1.5
  text "-" at 106.746,-65.5 h1.5
  text "NPTH" at 136.607,-65.5 h1.5
  text "Round" at 148.774,-65.5 h1.5
  text "R" at 21.126,-65.6 h1.67
  text "2" at 33.917,-69.25 h1.5
  text "1.143mm (45.00mil)" at 49.863,-69.25 h1.5
  text "-" at 78.304,-69.25 h1.5
  text "-" at 106.746,-69.25 h1.5
  text "PTH" at 136.607,-69.25 h1.5
  text "Round" at 148.774,-69.25 h1.5
  text "V" at 21.126,-69.35 h1.67
  text "3" at 33.917,-73 h1.5
  text "1.600mm (62.99mil)" at 49.863,-73 h1.5
  text "-" at 78.304,-73 h1.5
  text "-" at 106.746,-73 h1.5
  text "NPTH" at 136.607,-73 h1.5
  text "Round" at 148.774,-73 h1.5
  text "4" at 33.917,-76.75 h1.5
  text "1.600mm (63.00mil)" at 49.863,-76.75 h1.5
  text "-" at 78.304,-76.75 h1.5
  text "-" at 106.746,-76.75 h1.5
  text "PTH" at 136.607,-76.75 h1.5
  text "Round" at 148.774,-76.75 h1.5
  text "M" at 21.126,-76.85 h1.67
  text "1" at 33.917,-80.5 h1.5
  text "2.362mm (93.00mil)" at 49.863,-80.5 h1.5
  text "-" at 78.304,-80.5 h1.5
  text "-" at 106.746,-80.5 h1.5
  text "NPTH" at 136.607,-80.5 h1.5
  text "Round" at 148.774,-80.5 h1.5
  text "O" at 21.126,-80.6 h1.67
  text "4" at 33.917,-84.25 h1.5
  text "2.362mm (93.00mil)" at 49.863,-84.25 h1.5
  text "-" at 78.304,-84.25 h1.5
  text "-" at 106.746,-84.25 h1.5
  text "PTH" at 136.607,-84.25 h1.5
  text "Round" at 148.774,-84.25 h1.5
  text "T" at 21.126,-84.35 h1.67
  text "3" at 33.917,-88 h1.5
  text "2.600mm (102.36mil)" at 49.863,-88 h1.5
  text "-" at 78.304,-88 h1.5
  text "-" at 106.746,-88 h1.5
  text "PTH" at 136.607,-88 h1.5
  text "Round" at 148.774,-88 h1.5
  text "4" at 33.917,-91.75 h1.5
  text "3.175mm (125.00mil)" at 49.863,-91.75 h1.5
  text "-" at 78.304,-91.75 h1.5
  text "-" at 106.746,-91.75 h1.5
  text "NPTH" at 136.607,-91.75 h1.5
  text "Round" at 148.774,-91.75 h1.5
  text "N" at 21.126,-91.85 h1.67
  text "4" at 33.917,-95.5 h1.5
  text "3.200mm (125.98mil)" at 49.863,-95.5 h1.5
  text "-" at 78.304,-95.5 h1.5
  text "-" at 106.746,-95.5 h1.5
  text "PTH" at 136.607,-95.5 h1.5
  text "Round" at 148.774,-95.5 h1.5
  text "4" at 33.917,-99.25 h1.5
  text "3.200mm (126.00mil)" at 49.863,-99.25 h1.5
  text "-" at 78.304,-99.25 h1.5
  text "-" at 106.746,-99.25 h1.5
  text "NPTH" at 136.607,-99.25 h1.5
  text "Round" at 148.774,-99.25 h1.5
  text "L" at 21.126,-99.35 h1.67
  text "3" at 33.917,-103 h1.5
  text "1.016mm (40.00mil)" at 49.863,-103 h1.5
  text "3.200mm (126.00mil)" at 78.304,-103 h1.5
  text "2.184mm (86.00mil)" at 106.746,-103 h1.5
  text "PTH" at 136.607,-103 h1.5
  text "Slot" at 148.774,-103 h1.5
  text "P" at 21.126,-103.1 h1.67
  text "1800 Total" at 33.917,-106.75 h1.5
  text "Slot definitions :" at 21.75,-110.074 h1.5
  text "Rout Path Length" at 47.147,-110.074 h1.5
  text "= Calculated from tool start centre position to tool end centre position." at 71.295,-110.074 h1.5
  text "Hole Length" at 47.147,-112.274 h1.5
  text "= Rout Path Length + Tool Size = Slot length as defined in the PCB layout" at 64.047,-112.274 h1.5

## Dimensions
0,72 to 100,72 on Sheet Graphics
0,72 to 102.5,72 on Sheet Graphics
202.5,72 to 205,72 on Sheet Graphics
0,72 to 0,0 on Sheet Graphics
-15,79.5 to 0,72 on Sheet Graphics
-15,79.5 to 320,79.5 on Sheet Graphics
-15,79.5 to -15,-11.5 on Sheet Graphics
-15,-11.5 to 0,0 on Sheet Graphics
305,0 to 306.25,-4 on Sheet Graphics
